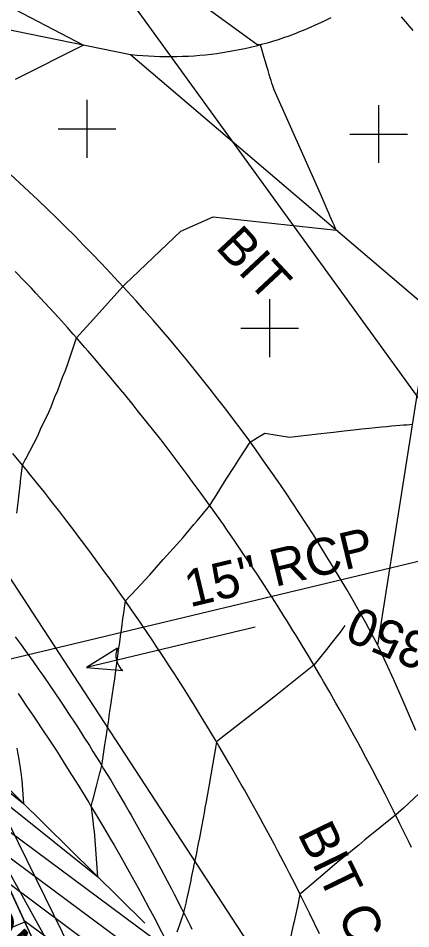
# Model space of a CAD drawing. Extents: x 487096 to 489566, y 221939 to 224454.
# Drawn here: x 488402.4 to 488436.3, y 223512.7 to 223591.5 of the extents above; entities that cross this region are included whole.
import ezdxf

# ---------------------------------------------------------------- set-up
doc = ezdxf.new("R2010")
doc.units = 0
for name, color, linetype in [('SV_BKLN_BKLN', 7, 'Continuous'), ('SV_BKLN_EARTH_TOP', 7, 'Continuous'), ('SV_DRAN_DRAN_TX', 7, 'Continuous'), ('SV_FENC_FENCES', 7, 'Continuous'), ('SV_PIPE_FLOW', 7, 'Continuous'), ('SV_PIPE_RC_15', 7, 'Continuous'), ('SV_PIPE_RC_TX', 7, 'Continuous'), ('SV_ROAD_BITRD', 7, 'Continuous'), ('SV_ROAD_GRAVRD', 7, 'Continuous'), ('SV_ROAD_ROAD_TX', 7, 'Continuous'), ('SV_ROWL_HWYLOC', 7, 'Continuous'), ('SV_SURF_INDEX_CONTOUR', 7, 'Continuous'), ('SV_SURF_INTER_CONTOUR', 7, 'Continuous'), ('SV_SURF_SPOT', 7, 'Continuous'), ('SV_TRAF_PVMTL', 7, 'Continuous'), ('SV_TREE_TREEVEG', 7, 'Continuous'), ('SV_UTOH_OVERHEAD_LINES', 7, 'Continuous')]:
    doc.layers.add(name, color=color, linetype=linetype)

msp = doc.modelspace()

# ---------------------------------------------------------------- linework, layer by layer
at = {"layer": 'SV_BKLN_BKLN'}
for points in [[(488433.505, 223537.205), (488432.978, 223538.178), (488432.444, 223539.147), (488431.903, 223540.112), (488431.355, 223541.073), (488430.8, 223542.03), (488430.239, 223542.983), (488429.67, 223543.932), (488429.095, 223544.876), (488428.512, 223545.817), (488427.923, 223546.753), (488427.328, 223547.685), (488426.725, 223548.613), (488426.116, 223549.536), (488425.5, 223550.455), (488424.877, 223551.37), (488424.248, 223552.28), (488423.613, 223553.185), (488422.971, 223554.086), (488422.322, 223554.982), (488421.667, 223555.873), (488421.005, 223556.759), (488420.337, 223557.641), (488419.663, 223558.518), (488418.982, 223559.39), (488418.295, 223560.257), (488417.602, 223561.119), (488416.903, 223561.976), (488416.197, 223562.828), (488415.485, 223563.675), (488414.767, 223564.517), (488414.044, 223565.353), (488413.314, 223566.184), (488412.578, 223567.01), (488411.836, 223567.831), (488411.088, 223568.646), (488410.334, 223569.456), (488409.575, 223570.26), (488408.81, 223571.059), (488408.038, 223571.852), (488407.262, 223572.639), (488406.479, 223573.421), (488405.691, 223574.198), (488404.897, 223574.968), (488404.098, 223575.733), (488403.293, 223576.492), (488402.483, 223577.245), (488401.668, 223577.992)], [(488395.978, 223530.274), (488413.334, 223513.157)]]:
    msp.add_lwpolyline(points, dxfattribs=at)
at = {"layer": 'SV_BKLN_EARTH_TOP'}
msp.add_lwpolyline([(488396.133, 223528.066), (488405.176, 223508.394), (488413.006, 223498.439), (488419.528, 223486.959), (488427.323, 223441.182)], dxfattribs=at)
at = {"layer": 'SV_FENC_FENCES'}
msp.add_lwpolyline([(488362.041, 223571.419), (488379.111, 223558.17), (488393.88, 223539.376), (488395.978, 223530.274), (488399.247, 223521.174), (488405.176, 223508.394), (488413.006, 223498.439), (488427.323, 223441.182)], dxfattribs=at)
at = {"layer": 'SV_PIPE_FLOW'}
for p, q in [((488422.874, 223538.78), (488408.285, 223535.284)), ((488410.971, 223536.958), (488408.285, 223535.284)), ((488408.285, 223535.284), (488411.438, 223535.009))]:
    msp.add_line(p, q, dxfattribs=at)
msp.add_arc((488412.467, 223536.286), 1.639, 155.87573, 231.07736, dxfattribs=at)
at = {"layer": 'SV_PIPE_RC_15'}
msp.add_lwpolyline([(488444.216, 223546.186), (488395.526, 223534.518)], dxfattribs=at)
at = {"layer": 'SV_ROAD_BITRD'}
for points in [[(488436.796, 223529.839), (488436.161, 223531.3), (488435.519, 223532.758), (488434.869, 223534.213), (488434.212, 223535.664), (488433.548, 223537.112), (488433.505, 223537.205), (488438.039, 223566.201), (488412.098, 223588.326), (488389.515, 223592.947), (488385.201, 223591.021), (488344.377, 223615.779), (488295.354, 223639.201), (488243.635, 223660.28)], [(488402.36, 223533.028), (488402.659, 223532.596), (488403.105, 223531.945), (488403.695, 223531.074), (488403.988, 223530.638), (488404.426, 223529.981), (488405.077, 223528.993), (488405.652, 223528.111), (488405.937, 223527.669), (488406.362, 223527.004), (488406.996, 223526.003), (488407.623, 223524.998), (488407.934, 223524.494), (488408.484, 223523.595), (488408.757, 223523.145), (488409.164, 223522.468), (488409.769, 223521.449), (488410.368, 223520.426), (488410.665, 223519.913), (488411.255, 223518.885), (488411.547, 223518.369), (488411.982, 223517.594), (488412.494, 223516.672), (488412.748, 223516.21), (488413.126, 223515.516), (488413.688, 223514.472), (488414.243, 223513.424), (488414.518, 223512.899), (488415.064, 223511.845)]]:
    msp.add_lwpolyline(points, dxfattribs=at)
at = {"layer": 'SV_ROAD_GRAVRD'}
msp.add_lwpolyline([(488429.419, 223591.524), (488428.977, 223591.302), (488428.532, 223591.087), (488428.084, 223590.878), (488427.632, 223590.678), (488427.176, 223590.484), (488426.718, 223590.298), (488426.257, 223590.119), (488425.793, 223589.948), (488425.326, 223589.784), (488424.857, 223589.628), (488424.385, 223589.48), (488423.911, 223589.339), (488423.435, 223589.206), (488422.957, 223589.08), (488422.476, 223588.963), (488421.994, 223588.853), (488421.51, 223588.751), (488421.025, 223588.656), (488420.538, 223588.57), (488420.05, 223588.492), (488419.56, 223588.421), (488419.069, 223588.358), (488418.578, 223588.304), (488418.086, 223588.257), (488417.593, 223588.218), (488417.099, 223588.187), (488416.605, 223588.165), (488416.111, 223588.15), (488415.616, 223588.143), (488415.122, 223588.144), (488414.627, 223588.153), (488414.133, 223588.17), (488413.639, 223588.196), (488413.146, 223588.229), (488412.653, 223588.27), (488412.161, 223588.319), (488412.098, 223588.326)], dxfattribs=at)
at = {"layer": 'SV_ROWL_HWYLOC'}
for points in [[(487756.919, 223854.031), (487819.736, 223823.932), (487982.506, 223759.36), (488009.692, 223754.735), (488041.144, 223750.633), (488071.96, 223735.453), (488100.921, 223722.744), (488124.658, 223715.601), (488155.682, 223709.246), (488178.896, 223706.069), (488296.161, 223658.564), (488379.396, 223617.166), (488410.154, 223595.683), (488443.8, 223549.214), (488472.236, 223469.86), (488477.064, 223418.158), (488475.622, 223352.082), (488474.079, 223317.483), (488463.166, 223231.249), (488461.577, 223189.461)], [(488362.041, 223571.419), (488379.111, 223558.17), (488393.88, 223539.376), (488394.741, 223535.644), (488413.006, 223498.439), (488420.164, 223469.81), (488427.323, 223441.182), (488428.59, 223411.485), (488428.888, 223402.557), (488428.648, 223363.443), (488428.288, 223340.613), (488424.744, 223306.137), (488415.388, 223241.145), (488415.007, 223209.78)]]:
    msp.add_lwpolyline(points, dxfattribs=at)
at = {"layer": 'SV_SURF_INDEX_CONTOUR'}
for points in [[(488430.65, 223538.917), (488430.239, 223538.353), (488429.55, 223537.481), (488429.066, 223536.836), (488427.96, 223535.493), (488424.485, 223532.711), (488423.676, 223532.08), (488419.976, 223529.197), (488419.837, 223529.087), (488419.532, 223528.851), (488419.444, 223528.319), (488419.44, 223528.294), (488419.252, 223527.171), (488419.233, 223527.067), (488419.223, 223527.011), (488419.048, 223525.98), (488419.021, 223525.832), (488418.956, 223525.481), (488418.643, 223523.685), (488418.536, 223523.126), (488418.461, 223522.703), (488418.372, 223522.248), (488418.238, 223521.502), (488418.169, 223521.157), (488418.056, 223520.538), (488417.954, 223520.035), (488417.897, 223519.76), (488417.834, 223519.419), (488417.796, 223519.214), (488417.582, 223518.198), (488417.521, 223517.874), (488417.356, 223517.113), (488417.306, 223516.85), (488417.189, 223516.32), (488417.015, 223515.535), (488416.997, 223515.447), (488416.905, 223515.04), (488416.898, 223515.002), (488416.685, 223514.07), (488416.673, 223514.035), (488416.67, 223514.027), (488416.479, 223513.448), (488416.331, 223513.018), (488416.116, 223512.38)], [(488415.584, 223510.692), (488412.717, 223512.796), (488398.182, 223523.608), (488398.256, 223523.367), (488395.89, 223522.479), (488380.62, 223517.26), (488374.461, 223510.159)]]:
    msp.add_lwpolyline(points, dxfattribs=at)
at = {"layer": 'SV_SURF_INTER_CONTOUR'}
for points in [[(488402.268, 223548.633), (488402.405, 223549.795), (488402.431, 223550.096), (488402.57, 223551.284), (488402.579, 223551.388), (488402.584, 223551.45), (488402.657, 223552.073), (488402.74, 223552.798), (488402.988, 223553.25), (488403.023, 223553.332), (488404.076, 223555.331), (488404.313, 223555.922), (488405.039, 223557.375), (488405.214, 223557.84), (488405.543, 223558.722), (488405.79, 223559.25), (488406.205, 223560.411), (488406.473, 223561.006), (488406.689, 223561.649), (488406.769, 223561.832), (488407.354, 223563.634), (488407.364, 223563.659), (488407.416, 223563.829), (488409.162, 223565.732), (488411.436, 223568.267), (488411.639, 223568.478), (488416.455, 223573.047), (488419.238, 223574.291), (488429.913, 223573.131), (488429.901, 223573.156), (488429.808, 223573.356), (488429.71, 223573.571), (488429.605, 223573.803), (488429.493, 223574.054), (488429.374, 223574.326), (488429.245, 223574.62), (488429.107, 223574.941), (488428.958, 223575.29), (488428.797, 223575.671), (488428.622, 223576.089), (488428.43, 223576.547), (488424.515, 223585.29), (488424.46, 223585.458), (488424.4, 223585.646), (488424.334, 223585.853), (488424.262, 223586.084), (488424.183, 223586.342), (488424.096, 223586.629), (488423.999, 223586.95), (488423.89, 223587.312), (488423.769, 223587.719), (488423.632, 223588.181), (488423.476, 223588.708), (488423.336, 223589.18), (488423.034, 223589.216), (488412.707, 223596.753)], [(488398.76, 223594.004), (488408.038, 223589.157), (488402.121, 223586.177)], [(488436.566, 223590.427), (488435.538, 223591.608)], [(488401.716, 223523.227), (488409.264, 223517.171), (488408.964, 223521.113), (488408.931, 223521.409), (488408.857, 223522.033), (488408.77, 223522.701), (488408.704, 223523.175), (488408.692, 223523.251), (488408.817, 223523.718), (488408.894, 223524.012), (488409.155, 223525.007), (488409.45, 223526.169), (488409.489, 223526.324), (488409.606, 223526.79), (488409.661, 223527.143), (488409.665, 223527.167), (488409.884, 223528.584), (488409.912, 223528.767), (488410.011, 223529.421), (488410.049, 223529.668), (488410.184, 223530.583), (488410.21, 223530.755), (488410.258, 223531.086), (488410.344, 223531.688), (488410.392, 223532.01), (488410.451, 223532.427), (488410.538, 223533.014), (488410.617, 223533.584), (488410.723, 223534.313), (488410.818, 223535.023), (488410.879, 223535.439), (488411, 223536.293), (488411.068, 223536.81), (488411.133, 223537.272), (488411.159, 223537.475), (488411.264, 223538.224), (488411.3, 223538.515), (488411.471, 223539.738), (488411.479, 223539.809), (488411.649, 223541.049), (488412.072, 223541.492), (488412.18, 223541.614), (488413.767, 223543.306), (488414.924, 223544.645), (488416.641, 223546.531), (488417.583, 223547.666), (488417.865, 223547.981), (488418.947, 223549.315), (488419.215, 223549.744), (488419.351, 223549.954), (488420.375, 223551.583), (488421.092, 223552.685), (488421.537, 223553.389), (488422.46, 223554.791), (488423.092, 223555.186), (488423.722, 223555.581), (488425.859, 223555.211), (488427.328, 223555.389), (488428.575, 223555.537), (488429.646, 223555.661), (488430.574, 223555.767), (488431.385, 223555.857), (488432.1, 223555.934), (488432.734, 223556.001), (488433.299, 223556.059), (488433.806, 223556.109), (488434.263, 223556.153), (488434.676, 223556.191), (488435.051, 223556.224), (488435.393, 223556.252), (488435.705, 223556.277), (488435.991, 223556.299), (488436.254, 223556.318), (488436.496, 223556.334)], [(488396.072, 223528.933), (488402.86, 223523.487), (488402.705, 223525.529), (488402.688, 223525.682), (488402.649, 223526.005), (488402.604, 223526.351), (488402.57, 223526.597), (488402.545, 223526.767), (488402.49, 223527.126), (488402.456, 223527.339), (488402.38, 223527.792), (488402.292, 223528.286)], [(488437.111, 223524.403), (488435.715, 223523.097), (488435.032, 223522.501), (488432.376, 223520.359), (488431.842, 223519.913), (488430.158, 223518.547), (488428.357, 223517.019), (488426.839, 223515.729), (488426.808, 223515.704), (488426.759, 223515.661), (488426.531, 223514.564), (488426.506, 223514.467), (488426.285, 223513.425), (488426.252, 223513.296), (488426.17, 223512.984), (488425.754, 223511.09)], [(488411.024, 223511.808), (488399.752, 223520.193), (488399.85, 223519.875), (488398.961, 223519.504), (488383.367, 223514.175), (488377.971, 223507.952)], [(488386.115, 223511.089), (488398.229, 223515.229), (488401.392, 223516.552), (488401.322, 223516.777), (488409.332, 223510.82)], [(488407.639, 223509.832), (488402.892, 223513.362), (488402.933, 223513.229), (488397.497, 223510.954)]]:
    msp.add_lwpolyline(points, dxfattribs=at)
at = {"layer": 'SV_SURF_SPOT'}
for p, q in [((488408.334, 223579.41), (488408.334, 223584.412)), ((488433.573, 223578.957), (488433.573, 223583.959)), ((488405.833, 223581.911), (488410.835, 223581.911)), ((488408.334, 223581.911), (488408.334, 223581.911)), ((488431.072, 223581.458), (488436.074, 223581.458)), ((488433.573, 223581.458), (488433.573, 223581.458)), ((488424.137, 223562.161), (488424.137, 223567.163)), ((488421.636, 223564.662), (488426.638, 223564.662)), ((488424.137, 223564.662), (488424.137, 223564.662))]:
    msp.add_line(p, q, dxfattribs=at)
at = {"layer": 'SV_TRAF_PVMTL'}
for points in [[(488436.401, 223519.704), (488436.194, 223520.134), (488435.882, 223520.779), (488435.409, 223521.744), (488434.842, 223522.884), (488434.556, 223523.453), (488434.123, 223524.305), (488433.687, 223525.156), (488433.467, 223525.58), (488433.025, 223526.427), (488432.802, 223526.85), (488432.466, 223527.484), (488432.015, 223528.326), (488431.788, 223528.747), (488431.445, 223529.377), (488430.927, 223530.32), (488430.462, 223531.156), (488430.228, 223531.573), (488429.875, 223532.197), (488429.342, 223533.132), (488428.803, 223534.064), (488428.532, 223534.529), (488427.486, 223536.293), (488426.956, 223537.172), (488426.422, 223538.047), (488426.153, 223538.484), (488425.612, 223539.355), (488425.339, 223539.79), (488424.928, 223540.441), (488424.376, 223541.306), (488424.099, 223541.737), (488423.68, 223542.383), (488423.047, 223543.349), (488422.48, 223544.204), (488422.194, 223544.63), (488421.764, 223545.269), (488421.114, 223546.223), (488420.458, 223547.173), (488420.127, 223547.647), (488419.537, 223548.486), (488419.24, 223548.904), (488418.792, 223549.531), (488418.116, 223550.466), (488417.434, 223551.398), (488417.091, 223551.862), (488416.401, 223552.787), (488416.053, 223553.248), (488415.53, 223553.938), (488414.905, 223554.751), (488414.591, 223555.157), (488414.118, 223555.764), (488413.403, 223556.67), (488412.683, 223557.571), (488412.321, 223558.02), (488411.593, 223558.915), (488411.227, 223559.36), (488410.675, 223560.026), (488409.934, 223560.91), (488409.561, 223561.35), (488409, 223562.008), (488408.436, 223562.662), (488408.152, 223562.989), (488407.478, 223563.76), (488407.138, 223564.144), (488406.628, 223564.718), (488405.858, 223565.574), (488405.082, 223566.426), (488404.692, 223566.849), (488403.908, 223567.693), (488403.514, 223568.113), (488402.92, 223568.74), (488402.124, 223569.571)], [(488428.442, 223512.231), (488427.604, 223513.959), (488427.179, 223514.82), (488426.75, 223515.679), (488426.534, 223516.108), (488426.099, 223516.965), (488425.88, 223517.392), (488425.549, 223518.033), (488425.105, 223518.885), (488424.882, 223519.311), (488424.545, 223519.948), (488424.035, 223520.902), (488423.578, 223521.748), (488423.348, 223522.17), (488423.001, 223522.802), (488422.476, 223523.748), (488421.947, 223524.691), (488421.68, 223525.162), (488420.722, 223526.829), (488420.237, 223527.66), (488419.748, 223528.488), (488419.502, 223528.901), (488419.008, 223529.726), (488418.759, 223530.137), (488418.384, 223530.753), (488417.881, 223531.573), (488417.627, 223531.982), (488417.246, 223532.593), (488416.67, 223533.509), (488416.153, 223534.32), (488415.894, 223534.724), (488415.503, 223535.33), (488414.912, 223536.235), (488414.316, 223537.138), (488414.016, 223537.588), (488413.48, 223538.385), (488413.211, 223538.783), (488412.805, 223539.379), (488412.193, 223540.269), (488411.575, 223541.156), (488411.265, 223541.598), (488410.64, 223542.479), (488410.326, 223542.918), (488409.853, 223543.575), (488408.72, 223545.125), (488408.148, 223545.895), (488407.572, 223546.662), (488407.283, 223547.045), (488406.701, 223547.808), (488406.409, 223548.188), (488405.969, 223548.757), (488405.379, 223549.512), (488405.083, 223549.889), (488404.637, 223550.452), (488403.964, 223551.294), (488403.361, 223552.039), (488403.059, 223552.41), (488402.603, 223552.965), (488401.916, 223553.794)], [(488402.119, 223537.939), (488402.636, 223537.232), (488402.978, 223536.759), (488403.658, 223535.809), (488404.163, 223535.093), (488404.498, 223534.614), (488405.162, 223533.651), (488405.492, 223533.168), (488406.145, 223532.198), (488406.792, 223531.223), (488407.219, 223530.57), (488407.502, 223530.133), (488407.878, 223529.549), (488408.065, 223529.257), (488408.535, 223528.515), (488408.846, 223528.019), (488409.463, 223527.023), (488409.769, 223526.523), (488410.377, 223525.52), (488410.977, 223524.513), (488411.373, 223523.839), (488411.636, 223523.388), (488411.984, 223522.786), (488412.157, 223522.485), (488412.448, 223521.975), (488413.025, 223520.953), (488413.595, 223519.927), (488413.971, 223519.241), (488414.22, 223518.782), (488414.55, 223518.17), (488414.715, 223517.863), (488415.265, 223516.826), (488415.628, 223516.132), (488415.868, 223515.669), (488416.186, 223515.05), (488416.345, 223514.74), (488416.699, 223514.042), (488416.933, 223513.575), (488417.244, 223512.952), (488417.398, 223512.641)]]:
    msp.add_lwpolyline(points, dxfattribs=at)
at = {"layer": 'SV_TREE_TREEVEG'}
msp.add_lwpolyline([(488469.572, 222626.729), (488414.357, 222775.799), (488391.306, 222875.646), (488384.757, 223013.776), (488396.275, 223079.007), (488413.65, 223210.141), (488414.482, 223247.549), (488427.956, 223341.619), (488424.883, 223443.612), (488411.442, 223499.763), (488395.395, 223528.757), (488373.339, 223524.504)], dxfattribs=at)
at = {"layer": 'SV_UTOH_OVERHEAD_LINES'}
msp.add_lwpolyline([(488477.012, 222631.438), (488424.125, 222778.25), (488391.68, 223012.955), (488449.873, 223205.72), (488469.995, 223438.334), (488349.561, 223622.886), (488159.178, 223693.118), (487993.175, 223755.783), (487804.196, 223830.216), (487742.262, 223860.212)], dxfattribs=at)

# ---------------------------------------------------------------- texts
at = {"layer": 'SV_DRAN_DRAN_TX'}
msp.add_text('STONE MASONRY', height=3.2, rotation=313.03859, dxfattribs=at).set_placement((488380.879, 223531.62))
at = {"layer": 'SV_PIPE_RC_TX'}
msp.add_text("15'' RCP", height=3.2, rotation=13.47655, dxfattribs=at).set_placement((488417.222, 223540.485))
at = {"layer": 'SV_ROAD_ROAD_TX'}
for s, rotation, p in [('BIT', 313.03859, (488419.355, 223571.619)), ('BIT CONC', 295.93586, (488426.511, 223520.93))]:
    msp.add_text(s, height=3.2, rotation=rotation, dxfattribs=at).set_placement(p)
at = {"layer": 'SV_SURF_INDEX_CONTOUR'}
msp.add_text('350', height=3.2, rotation=157.19275, dxfattribs=at).set_placement((488438.302, 223537.891))

doc.saveas('drawing.dxf')
